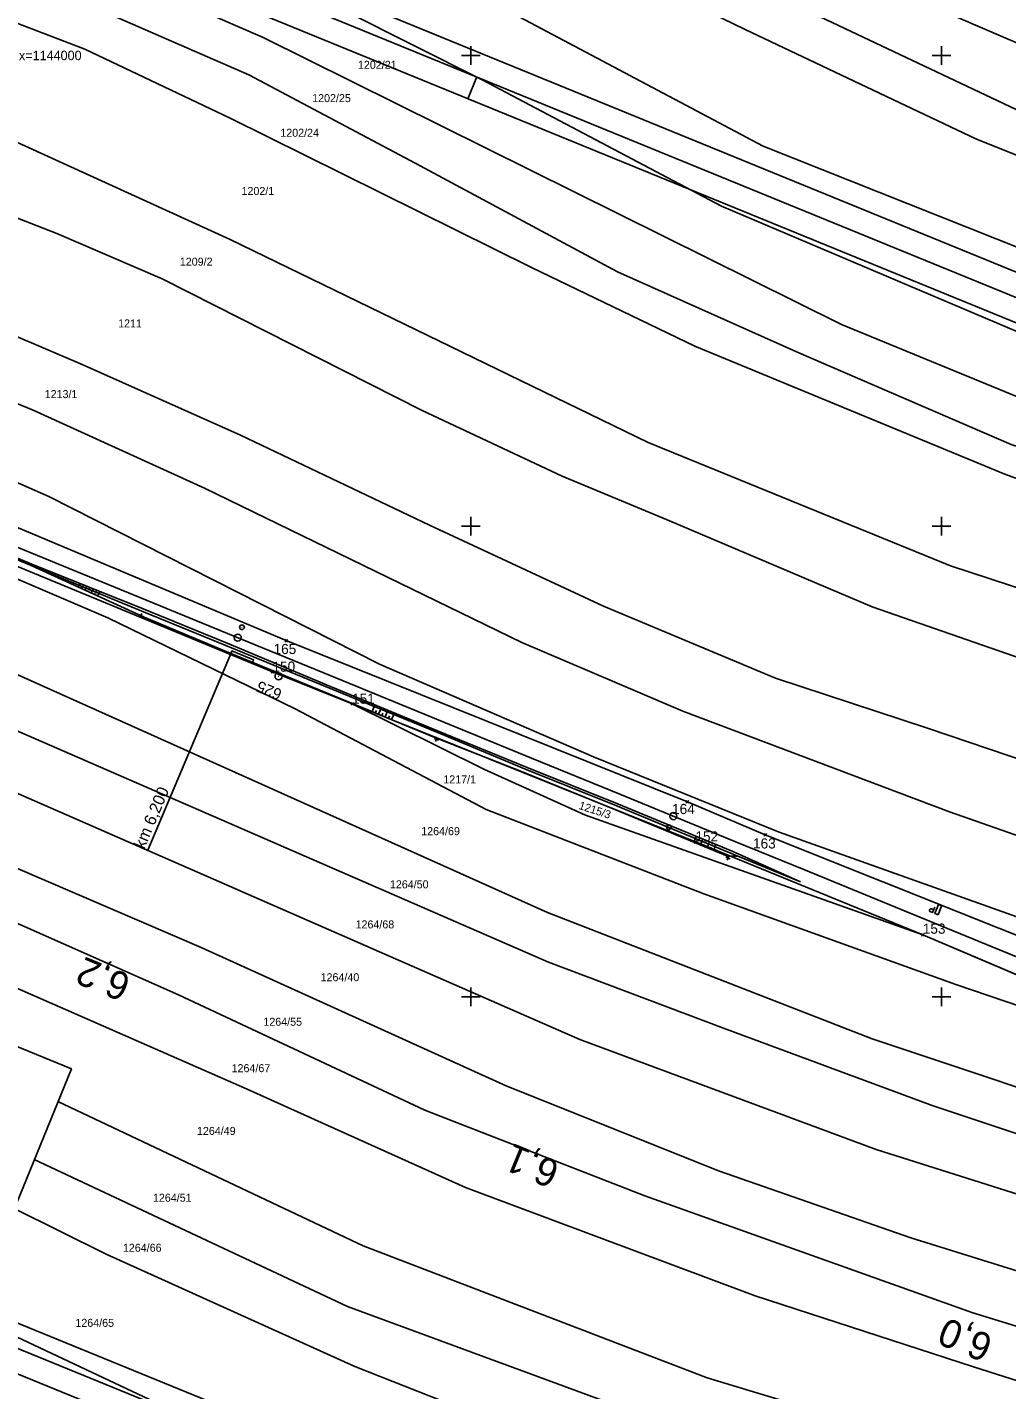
# Model space of a CAD drawing. Extents: x -779302 to -774398, y -1144902 to -1142831.
# Drawn here: x -776394.2 to -776186.1, y -1144283.5 to -1143994 of the extents above; entities that cross this region are included whole.
import ezdxf

# ---------------------------------------------------------------- set-up
doc = ezdxf.new("R2010")
doc.units = 0
for name, color, linetype in [('hektosit - Vrstva 5', 7, 'Continuous'), ('Hranice parcel', 7, 'Continuous'), ('legenda - Vrstva 7', 7, 'Continuous'), ('legenda I_5_2 - Vrstva 53', 7, 'Continuous'), ('Parcelní čísla', 7, 'Continuous'), ('SŽDC', 7, 'Continuous'), ('Vrstva 1', 7, 'Continuous'), ('zjednodus_g_situ-seda - Vrstva 1', 7, 'Continuous'), ('zjednodus_g_situ-seda - Vrstva 33', 7, 'Continuous'), ('zjednodus_g_situ-seda - Vrstva 48', 7, 'Continuous'), ('zjednodus_g_situ-seda - Vrstva 49', 7, 'Continuous'), ('zjednodus_g_situ-seda - Vrstva 63', 7, 'Continuous'), ('zjednodus_g_situ-seda - Vrstva 7', 7, 'Continuous'), ('zjednodus_g_situ-seda - Vrstva 9', 7, 'Continuous')]:
    doc.layers.add(name, color=color, linetype=linetype)

msp = doc.modelspace()

# ---------------------------------------------------------------- linework, layer by layer
at = {"layer": 'hektosit - Vrstva 5'}
for p, q in [((-776300, -1143998), (-776300, -1144002)), ((-776200, -1143998), (-776200, -1144002)), ((-776302, -1144000), (-776298, -1144000)), ((-776202, -1144000), (-776198, -1144000)), ((-776300, -1144098), (-776300, -1144102)), ((-776200, -1144098), (-776200, -1144102)), ((-776302, -1144100), (-776298, -1144100)), ((-776202, -1144100), (-776198, -1144100)), ((-776300, -1144198), (-776300, -1144202)), ((-776200, -1144198), (-776200, -1144202)), ((-776302, -1144200), (-776298, -1144200)), ((-776202, -1144200), (-776198, -1144200))]:
    msp.add_line(p, q, dxfattribs=at)
at = {"layer": 'Hranice parcel'}
msp.add_line((-776203.96, -1144186.83), (-776126.28, -1144219.86), dxfattribs=at)
for points in [[(-776130.8, -1144031.65), (-776167.18, -1144019.46), (-776296.05, -1143958.5), (-776332.97, -1143941.86), (-776361.98, -1143930.46), (-776408.9, -1143915.72), (-776494.43, -1143891.48), (-776517.13, -1143883.53)], [(-776127.12, -1144041.75), (-776162.43, -1144029.85), (-776192.7, -1144017.69), (-776241.68, -1143994.5), (-776321.54, -1143955.7), (-776383.3, -1143931.9), (-776418.7, -1143920.93), (-776489.84, -1143902.44), (-776518.46, -1143894.36), (-776535.81, -1143887.79)], [(-776119.18, -1144063.71), (-776170, -1144046.22), (-776237.87, -1144019.26), (-776326.2, -1143972.4), (-776378, -1143951.65), (-776436.08, -1143933.84), (-776517.12, -1143911.82), (-776566.02, -1143893.46)], [(-776111.68, -1144084.62), (-776181.26, -1144059.74), (-776246.74, -1144031.99), (-776297.59, -1144005.18), (-776341.39, -1143983.08), (-776381.58, -1143964.67), (-776441.43, -1143945.4), (-776519.5, -1143926.07), (-776584.9, -1143900.82)], [(-776593.79, -1143913.81), (-776553, -1143929.07), (-776527.51, -1143937.51), (-776470.29, -1143952.19), (-776437.66, -1143960.66), (-776390.42, -1143976.01), (-776344.1, -1143996.17), (-776221.27, -1144057.17), (-776180.2, -1144074), (-776142.2, -1144086.85), (-776107.01, -1144097.64)], [(-776360.45, -1143916.55), (-776326.79, -1143929.74), (-776297.56, -1143943.4), (-776248.62, -1143967.36), (-776202.79, -1143989.23), (-776167.32, -1144004.47), (-776139.33, -1144015.17), (-776136.5, -1144016)], [(-776103.17, -1144108.34), (-776139.62, -1144097.29), (-776185.19, -1144082.67), (-776230.28, -1144063.14), (-776268.85, -1144045.98), (-776311.69, -1144022.93), (-776347.15, -1144004.12), (-776382.3, -1143988.84), (-776427.82, -1143973.66), (-776507.88, -1143951.31), (-776536.14, -1143944), (-776596.43, -1143923.1)], [(-776098.85, -1144120.12), (-776143.82, -1144104.66), (-776186.51, -1144088.97), (-776252.37, -1144061.74), (-776287.1, -1144045.07), (-776351.09, -1144013.34), (-776382, -1143998.69), (-776410.54, -1143987.67), (-776454.04, -1143974.87), (-776495.11, -1143963.98), (-776524.93, -1143955.67), (-776598.61, -1143932.15)], [(-776600.02, -1143957.46), (-776528.66, -1143976.76), (-776457.94, -1143997.05), (-776442.28, -1144001.65), (-776398.64, -1144017.46), (-776351.09, -1144039.08), (-776262.34, -1144082.22), (-776198.07, -1144108.44), (-776142.1, -1144126.74), (-776090.77, -1144146.14)], [(-776599.74, -1143971.88), (-776539.25, -1143987.71), (-776480.91, -1144004.77), (-776433.76, -1144019.99), (-776387.97, -1144037.81), (-776365.6, -1144047.46), (-776310.35, -1144075.44), (-776280.61, -1144089.36), (-776258.25, -1144098.68), (-776214.75, -1144117.12), (-776097.7, -1144157.79)], [(-776601.27, -1143990.4), (-776527.05, -1144013.4), (-776476.25, -1144029.92), (-776451.83, -1144038), (-776413.3, -1144052.52), (-776382.54, -1144065.64), (-776348.92, -1144080.63), (-776308.77, -1144099.81), (-776271.78, -1144116.96), (-776235.24, -1144132.31), (-776202.98, -1144142.91), (-776103.02, -1144176.77)], [(-776603.25, -1144004.14), (-776531.61, -1144026.86), (-776500.12, -1144036.38), (-776435.33, -1144057.94), (-776392.95, -1144075.37), (-776356.59, -1144091.91), (-776289.18, -1144124.7), (-776254.94, -1144139.28), (-776198.32, -1144160.66), (-776146.7, -1144178.71), (-776104.57, -1144192.02)], [(-776113.15, -1144215.23), (-776237.42, -1144165.58), (-776253.98, -1144158.55), (-776339.24, -1144124.31), (-776431.42, -1144085.55), (-776524.5, -1144047.63), (-776566.07, -1144030.95)], [(-776104.82, -1144208.77), (-776145.81, -1144196.56), (-776234.45, -1144165.02), (-776273.96, -1144148.97), (-776319.4, -1144129.31), (-776389.63, -1144093.66), (-776429.56, -1144076.12), (-776519.73, -1144046.81), (-776566.07, -1144030.95)], [(-776606.26, -1144039.66), (-776542.86, -1144059.4), (-776473.03, -1144080.58), (-776435.07, -1144094.71), (-776377.12, -1144119.5), (-776337.3, -1144138.78), (-776296.76, -1144160.19), (-776250.47, -1144178.1), (-776196.94, -1144197.35), (-776161.72, -1144209.31), (-776126.28, -1144219.86)], [(-776527.2, -1144055.02), (-776434.38, -1144092.81), (-776342.13, -1144130.92), (-776325.22, -1144137.73)], [(-776110.54, -1144243.08), (-776159.55, -1144227.35), (-776214.73, -1144208.93), (-776283.73, -1144182.09), (-776414.91, -1144123.19), (-776432.86, -1144115.28), (-776478.51, -1144099.13), (-776510.43, -1144089.03), (-776541.53, -1144079.23), (-776582.13, -1144067.05), (-776608.45, -1144059.24)], [(-776609.22, -1144072.59), (-776549.62, -1144089.18), (-776477.02, -1144111.9), (-776421.35, -1144132.65), (-776283.48, -1144192.64), (-776246.29, -1144206.67), (-776201.94, -1144223.07), (-776173.05, -1144232.7), (-776113.8, -1144251.1)], [(-776118.46, -1144262.59), (-776213.85, -1144232.45), (-776276.83, -1144209.03), (-776421.73, -1144145.66), (-776463.81, -1144128.69), (-776555.71, -1144099.28), (-776609.79, -1144083.15)], [(-776610.76, -1144099.41), (-776538.78, -1144121.66), (-776471.83, -1144143.05), (-776416.15, -1144164.19), (-776357.31, -1144189.49), (-776292.36, -1144218.98), (-776247.15, -1144237), (-776206.49, -1144251.17), (-776124.24, -1144276.84)], [(-776611.4, -1144111.19), (-776509.83, -1144141.71), (-776435.48, -1144167.03), (-776362.11, -1144199.54), (-776309.74, -1144224.06), (-776263.02, -1144242.23), (-776193.31, -1144267.08), (-776128.39, -1144287.08)], [(-776132.3, -1144298.01), (-776193.18, -1144278.57), (-776239.59, -1144263.48), (-776301.12, -1144240.48), (-776347.51, -1144219.6), (-776446.62, -1144176.16), (-776482.94, -1144162.91), (-776612.01, -1144123.26)], [(-776325.22, -1144137.73), (-776252.27, -1144167.08), (-776203.96, -1144186.83)], [(-776325.22, -1144137.73), (-776297.26, -1144151.64), (-776275.64, -1144161.42), (-776203.96, -1144186.83)], [(-776387.71, -1144222.25), (-776322.84, -1144252.89), (-776249.8, -1144280.91), (-776136.12, -1144315.24)], [(-776392.74, -1144234.57), (-776326.16, -1144265.8), (-776260.62, -1144289.93), (-776206.39, -1144307.32), (-776138.04, -1144328.07)], [(-776139.95, -1144340.89), (-776219.46, -1144316.38), (-776263.77, -1144302.5), (-776324.6, -1144278.51), (-776377.44, -1144254.65), (-776396.98, -1144244.94)], [(-776143.31, -1144363.37), (-776191.33, -1144349.34), (-776249.99, -1144330.39), (-776319.63, -1144305.99), (-776364.66, -1144287.25), (-776444.24, -1144249.74)]]:
    msp.add_lwpolyline(points, dxfattribs=at)
at = {"layer": 'legenda - Vrstva 7'}
msp.add_lwpolyline([(-776405.43, -1144265.6), (-776482.49, -1144234.1), (-776461.9, -1144183.75), (-776384.84, -1144215.25)], close=True, dxfattribs=at)
at = {"layer": 'legenda I_5_2 - Vrstva 53'}
msp.add_lwpolyline([(-776431.42, -1144085.55), (-776339.24, -1144124.31), (-776253.98, -1144158.55), (-776237.42, -1144165.58), (-776113.15, -1144215.23), (-776109.59, -1144216.67), (-776105.05, -1144218.51), (-776101.21, -1144220.07), (-776096.42, -1144222.78), (-776095.57, -1144223.11), (-776096.98, -1144226.78), (-776098.59, -1144230.98), (-776104.51, -1144228.21), (-776116.08, -1144223.44), (-776126.28, -1144219.86), (-776203.96, -1144186.83), (-776252.27, -1144167.08), (-776325.22, -1144137.73), (-776342.13, -1144130.92), (-776434.38, -1144092.81)], dxfattribs=at)
at = {"layer": 'SŽDC'}
for p, q in [((-776339.04, -1144124.51), (-776339.54, -1144124.01)), ((-776339.04, -1144124.11), (-776339.54, -1144124.61)), ((-776339.44, -1144124.51), (-776338.94, -1144124.01)), ((-776339.44, -1144124.11), (-776338.94, -1144124.61)), ((-776339.24, -1144124.31), (-776339.24, -1144124.31)), ((-776341.93, -1144131.12), (-776342.43, -1144130.62)), ((-776341.93, -1144130.72), (-776342.43, -1144131.22)), ((-776342.33, -1144131.12), (-776341.83, -1144130.62)), ((-776342.33, -1144130.72), (-776341.83, -1144131.22)), ((-776342.13, -1144130.92), (-776342.13, -1144130.92)), ((-776325.02, -1144137.93), (-776325.52, -1144137.43)), ((-776325.02, -1144137.53), (-776325.52, -1144138.03)), ((-776325.42, -1144137.93), (-776324.92, -1144137.43)), ((-776325.42, -1144137.53), (-776324.92, -1144138.03)), ((-776325.22, -1144137.73), (-776325.22, -1144137.73)), ((-776253.78, -1144158.75), (-776254.28, -1144158.25)), ((-776253.78, -1144158.35), (-776254.28, -1144158.85)), ((-776254.18, -1144158.75), (-776253.68, -1144158.25)), ((-776254.18, -1144158.35), (-776253.68, -1144158.85)), ((-776253.98, -1144158.55), (-776253.98, -1144158.55)), ((-776252.07, -1144167.28), (-776252.57, -1144166.78)), ((-776252.07, -1144166.88), (-776252.57, -1144167.38)), ((-776252.47, -1144167.28), (-776251.97, -1144166.78)), ((-776252.47, -1144166.88), (-776251.97, -1144167.38)), ((-776252.27, -1144167.08), (-776252.27, -1144167.08)), ((-776237.22, -1144165.78), (-776237.72, -1144165.28)), ((-776237.22, -1144165.38), (-776237.72, -1144165.88)), ((-776237.62, -1144165.78), (-776237.12, -1144165.28)), ((-776237.62, -1144165.38), (-776237.12, -1144165.88)), ((-776237.42, -1144165.58), (-776237.42, -1144165.58)), ((-776203.76, -1144187.03), (-776204.26, -1144186.53)), ((-776203.76, -1144186.63), (-776204.26, -1144187.13)), ((-776204.16, -1144187.03), (-776203.66, -1144186.53)), ((-776204.16, -1144186.63), (-776203.66, -1144187.13)), ((-776203.96, -1144186.83), (-776203.96, -1144186.83))]:
    msp.add_line(p, q, dxfattribs=at)
for points in [[(-776098.59, -1144230.98), (-776104.51, -1144228.21), (-776116.08, -1144223.44), (-776126.28, -1144219.86), (-776203.96, -1144186.83), (-776252.27, -1144167.08), (-776325.22, -1144137.73), (-776342.13, -1144130.92), (-776434.38, -1144092.81), (-776527.2, -1144055.02), (-776604.66, -1144024.21), (-776606.85, -1144023.34), (-776609.89, -1144021.72), (-776627.91, -1144012.39), (-776712.36, -1143980.08), (-776747.29, -1143966.09), (-776893.47, -1143907.54), (-776959.34, -1143880.62), (-776970.83, -1143876.37), (-776982.48, -1143870.69)], [(-776932.26, -1143880.54), (-776911.85, -1143884.6), (-776911.17, -1143889.61), (-776861.29, -1143910.51), (-776802.08, -1143934.12), (-776755.18, -1143951.9), (-776617.86, -1144008.92), (-776606.8, -1144013.63), (-776604, -1144014.82), (-776566.07, -1144030.95), (-776524.5, -1144047.63), (-776431.42, -1144085.55), (-776339.24, -1144124.31), (-776253.98, -1144158.55), (-776237.42, -1144165.58), (-776113.15, -1144215.23), (-776109.59, -1144216.67), (-776105.05, -1144218.51), (-776101.21, -1144220.07), (-776096.42, -1144222.78), (-776095.57, -1144223.11)]]:
    msp.add_lwpolyline(points, dxfattribs=at)
at = {"layer": 'Vrstva 1'}
msp.add_line((-776300.61, -1144009.19), (-776298.72, -1144004.56), dxfattribs=at)
for points in [[(-775713.68, -1144238.31), (-776879.99, -1143761.57), (-776992.36, -1144036.48), (-775826.05, -1144513.22)], [(-775828.78, -1144506.7), (-776985.84, -1144033.74), (-776877.25, -1143768.09), (-775720.2, -1144241.05)], [(-775726.71, -1144243.78), (-776684.76, -1143852.17), (-776789.57, -1144108.58), (-775831.52, -1144500.19)], [(-775831.52, -1144500.19), (-776789.57, -1144108.58), (-776684.76, -1143852.17), (-775726.71, -1144243.78)]]:
    msp.add_lwpolyline(points, close=True, dxfattribs=at)
at = {"layer": 'zjednodus_g_situ-seda - Vrstva 1'}
msp.add_lwpolyline([(-776044.9, -1144248.56), (-776062.23, -1144241.45), (-776078.99, -1144234.58), (-776085.49, -1144231.92), (-776091.15, -1144229.58), (-776100.22, -1144225.86), (-776117.47, -1144218.8), (-776139.19, -1144209.89), (-776163.33, -1144200), (-776180.57, -1144192.93), (-776204.58, -1144183.08), (-776229.27, -1144172.96), (-776243.87, -1144166.96), (-776268.36, -1144156.92), (-776287.1, -1144149.26), (-776305.75, -1144141.61), (-776329.89, -1144131.72), (-776350.5, -1144123.27), (-776368.76, -1144115.79), (-776392.07, -1144106.25), (-776411.79, -1144098.15)], dxfattribs=at)
at = {"layer": 'zjednodus_g_situ-seda - Vrstva 33'}
msp.add_lwpolyline([(-776201.42, -1144180.9), (-776201.9, -1144182.06), (-776202.38, -1144181.86), (-776202.51, -1144181.75), (-776202.53, -1144181.52), (-776202.49, -1144181.42), (-776202.31, -1144181.27), (-776202.14, -1144181.29), (-776201.66, -1144181.49)], dxfattribs=at)
msp.add_lwpolyline([(-776200.72, -1144182.54), (-776201.41, -1144182.25), (-776200.65, -1144180.39), (-776199.96, -1144180.67)], close=True, dxfattribs=at)
at = {"layer": 'zjednodus_g_situ-seda - Vrstva 48'}
for p, q in [((-776382.99, -1144112.18), (-776383.15, -1144112.59)), ((-776382.29, -1144112.46), (-776382.38, -1144112.67)), ((-776383.37, -1144112.96), (-776383.19, -1144112.57)), ((-776382.68, -1144113.27), (-776382.59, -1144113.06)), ((-776382, -1144113.58), (-776381.8, -1144113.14)), ((-776381.6, -1144112.74), (-776381.77, -1144113.16)), ((-776381.32, -1144113.89), (-776381.21, -1144113.66)), ((-776380.9, -1144113.02), (-776380.99, -1144113.23)), ((-776380.64, -1144114.2), (-776380.41, -1144113.71)), ((-776380.21, -1144113.3), (-776380.38, -1144113.73)), ((-776379.96, -1144114.51), (-776379.84, -1144114.26)), ((-776379.51, -1144113.58), (-776379.6, -1144113.8)), ((-776379.27, -1144114.82), (-776379.03, -1144114.28)), ((-776378.82, -1144113.86), (-776378.99, -1144114.3)), ((-776320.97, -1144139.38), (-776320.53, -1144138.3)), ((-776320.38, -1144137.94), (-776320.53, -1144138.3)), ((-776319.69, -1144138.23), (-776319.76, -1144138.41)), ((-776319, -1144138.51), (-776319.14, -1144138.87)), ((-776320.28, -1144139.66), (-776320.06, -1144139.13)), ((-776319.59, -1144139.95), (-776319.14, -1144138.87)), ((-776318.89, -1144140.24), (-776318.67, -1144139.7)), ((-776318.3, -1144138.8), (-776318.38, -1144138.98)), ((-776318.2, -1144140.52), (-776317.76, -1144139.44)), ((-776317.61, -1144139.09), (-776317.76, -1144139.44)), ((-776317.51, -1144140.81), (-776317.28, -1144140.27)), ((-776316.92, -1144139.38), (-776316.99, -1144139.55)), ((-776316.81, -1144141.09), (-776316.37, -1144140.02)), ((-776316.23, -1144139.66), (-776316.37, -1144140.02)), ((-776252.58, -1144167.13), (-776252.26, -1144166.36)), ((-776252.09, -1144165.89), (-776252.27, -1144166.35)), ((-776251.89, -1144167.42), (-776251.73, -1144167.03)), ((-776251.39, -1144166.18), (-776251.49, -1144166.41)), ((-776251.2, -1144167.7), (-776250.88, -1144166.93)), ((-776250.7, -1144166.47), (-776250.89, -1144166.93)), ((-776250.01, -1144166.75), (-776250.1, -1144166.99)), ((-776249.81, -1144168.27), (-776249.49, -1144167.51)), ((-776249.31, -1144167.04), (-776249.51, -1144167.51)), ((-776248.62, -1144167.33), (-776248.72, -1144167.56)), ((-776250.5, -1144167.99), (-776250.35, -1144167.6)), ((-776249.12, -1144168.56), (-776248.96, -1144168.18)), ((-776248.42, -1144168.85), (-776248.11, -1144168.09)), ((-776247.93, -1144167.61), (-776248.12, -1144168.08))]:
    msp.add_line(p, q, dxfattribs=at)
at = {"layer": 'zjednodus_g_situ-seda - Vrstva 49'}
for points in [[(-776229.97, -1144175.53), (-776243.26, -1144170.11), (-776269.19, -1144159.31), (-776288.26, -1144151.69), (-776307.22, -1144143.79), (-776330.9, -1144134.03), (-776352.06, -1144125.33), (-776369.55, -1144118.18), (-776393.41, -1144108.37), (-776413.17, -1144100.24), (-776431.5, -1144092.78), (-776455.03, -1144083.03)], [(-776229.97, -1144175.53), (-776244.46, -1144169.05), (-776268.99, -1144158.9), (-776288, -1144151.25), (-776307.06, -1144143.46), (-776330.66, -1144133.68), (-776351.74, -1144124.88), (-776369.61, -1144117.58), (-776393.25, -1144108.04), (-776412.87, -1144099.93), (-776431.26, -1144092.36), (-776455.03, -1144083.03)], [(-776243.26, -1144170.11), (-776245.47, -1144170.07), (-776269.37, -1144160.19), (-776288.86, -1144152.25), (-776307.67, -1144144.86), (-776331.37, -1144135.1), (-776352.31, -1144126.49), (-776369.36, -1144119.35), (-776393.41, -1144108.37)]]:
    msp.add_lwpolyline(points, dxfattribs=at)
at = {"layer": 'zjednodus_g_situ-seda - Vrstva 63'}
msp.add_line((-776340.8, -1144131.91), (-776340.89, -1144131.87), dxfattribs=at)
msp.add_circle((-776340.84, -1144131.89), 0.756, dxfattribs=at)
at = {"layer": 'zjednodus_g_situ-seda - Vrstva 7'}
for p, q in [((-776369.61, -1144119.21), (-776370.53, -1144118.83)), ((-776370.26, -1144119.48), (-776369.88, -1144118.55)), ((-776348.57, -1144121.5), (-776348.66, -1144121.46)), ((-776306.85, -1144145.45), (-776307.77, -1144145.08)), ((-776307.5, -1144145.73), (-776307.12, -1144144.8)), ((-776257.85, -1144163.97), (-776257.95, -1144163.93)), ((-776244.87, -1144170.7), (-776245.79, -1144170.32)), ((-776245.52, -1144170.97), (-776245.14, -1144170.04))]:
    msp.add_line(p, q, dxfattribs=at)
for centre, radius in [((-776348.61, -1144121.48), 0.5), ((-776349.51, -1144123.68), 0.75), ((-776256.95, -1144161.6), 0.75), ((-776257.9, -1144163.95), 0.5)]:
    msp.add_circle(centre, radius, dxfattribs=at)
at = {"layer": 'zjednodus_g_situ-seda - Vrstva 9'}
msp.add_line((-776350.87, -1144126.78), (-776368.59, -1144168.83), dxfattribs=at)
msp.add_lwpolyline([(-776351.21, -1144127.61), (-776350.98, -1144127.06), (-776350.76, -1144126.5), (-776346.13, -1144128.4), (-776346.36, -1144128.95), (-776350.98, -1144127.06)], dxfattribs=at)

# ---------------------------------------------------------------- texts
at = {"layer": 'hektosit - Vrstva 5'}
msp.add_text('x=1144000', height=2, dxfattribs=at).set_placement((-776396, -1144001))
at = {"layer": 'Parcelní čísla'}
for s, p in [('1202/21', (-776323.98, -1144002.84)), ('1202/25', (-776333.7, -1144009.91)), ('1202/24', (-776340.47, -1144017.27)), ('1202/1', (-776348.71, -1144029.64)), ('1209/2', (-776361.82, -1144044.66)), ('1211', (-776374.92, -1144057.77)), ('1213/1', (-776390.53, -1144072.79)), ('1217/1', (-776305.84, -1144154.64)), ('1264/69', (-776310.53, -1144165.64)), ('1264/50', (-776317.18, -1144176.94)), ('1264/68', (-776324.48, -1144185.45)), ('1264/40', (-776331.91, -1144196.67)), ('1264/55', (-776344.07, -1144206.13)), ('1264/67', (-776350.82, -1144215.99)), ('1264/49', (-776358.18, -1144229.32)), ('1264/51', (-776367.53, -1144243.51)), ('1264/66', (-776373.91, -1144254.14)), ('1264/65', (-776384.01, -1144270.09))]:
    msp.add_text(s, height=1.7, dxfattribs=at).set_placement(p)
msp.add_text('1215/3', height=1.7, rotation=342, dxfattribs=at).set_placement((-776277.19, -1144160.04))
at = {"layer": 'SŽDC'}
for s, p in [('165', (-776341.9, -1144127.17)), ('150', (-776342.13, -1144130.92)), ('151', (-776325.22, -1144137.72)), ('164', (-776257.24, -1144161.16)), ('152', (-776252.27, -1144166.98)), ('163', (-776240.03, -1144168.47)), ('153', (-776203.96, -1144186.58))]:
    msp.add_text(s, height=2.16, dxfattribs=at).set_placement(p)
at = {"layer": 'zjednodus_g_situ-seda - Vrstva 63'}
msp.add_text('625', height=2.4, rotation=157.7213, dxfattribs=at).set_placement((-776339.92, -1144134.83))
at = {"layer": 'zjednodus_g_situ-seda - Vrstva 7'}
for s, rotation, p in [('6,2', 157.7241, (-776371.82, -1144195.57)), ('6,1', 157.6981, (-776280.74, -1144235.26)), ('6,0', 157.7045, (-776188.67, -1144272.2))]:
    msp.add_text(s, height=6, rotation=rotation, dxfattribs=at).set_placement(p)
at = {"layer": 'zjednodus_g_situ-seda - Vrstva 9'}
msp.add_text('km 6,200', height=2.5, rotation=67.1471, dxfattribs=at).set_placement((-776369.37, -1144168.73))

doc.saveas('drawing.dxf')
